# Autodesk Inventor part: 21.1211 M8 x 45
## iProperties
Created: 2006-02
Part Number: 21.1211 M8 x 45
Material: Steel, Mild
Description: Cylinder Head Cap Screw
Document SubType Name: Modeling
Standard: DIN 7984
Designer: Andy Moles
Standards Organization: DIN
Language: en-US
Size Designation: M8 x 45
Categories: <MemberInstance><Categories><Category DisplayName="Fasteners" InternalName="e4da775c-781d-43d5-af7c-5136215cf5a6" Mnemonic="FSTN"><Category DisplayName="Bolts"
Density: 7.86 g/cm^3
Mass: 22.1402 g
Surface Area: 16.4599 cm^2
Volume: 2.81682 cm^3
Author: Andy Moles
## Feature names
1. Body [Revolution]
2. Slot [Extrusion]
3. Fillet1
4. Chamfer1
